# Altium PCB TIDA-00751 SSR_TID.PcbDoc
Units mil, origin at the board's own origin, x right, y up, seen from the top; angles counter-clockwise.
Board outline 5000 x 2000 mil, 2 copper layers (Top Layer, Bottom Layer), stack 62 mil thick; 77 components, 33 nets, 159 pads, 254 vias.
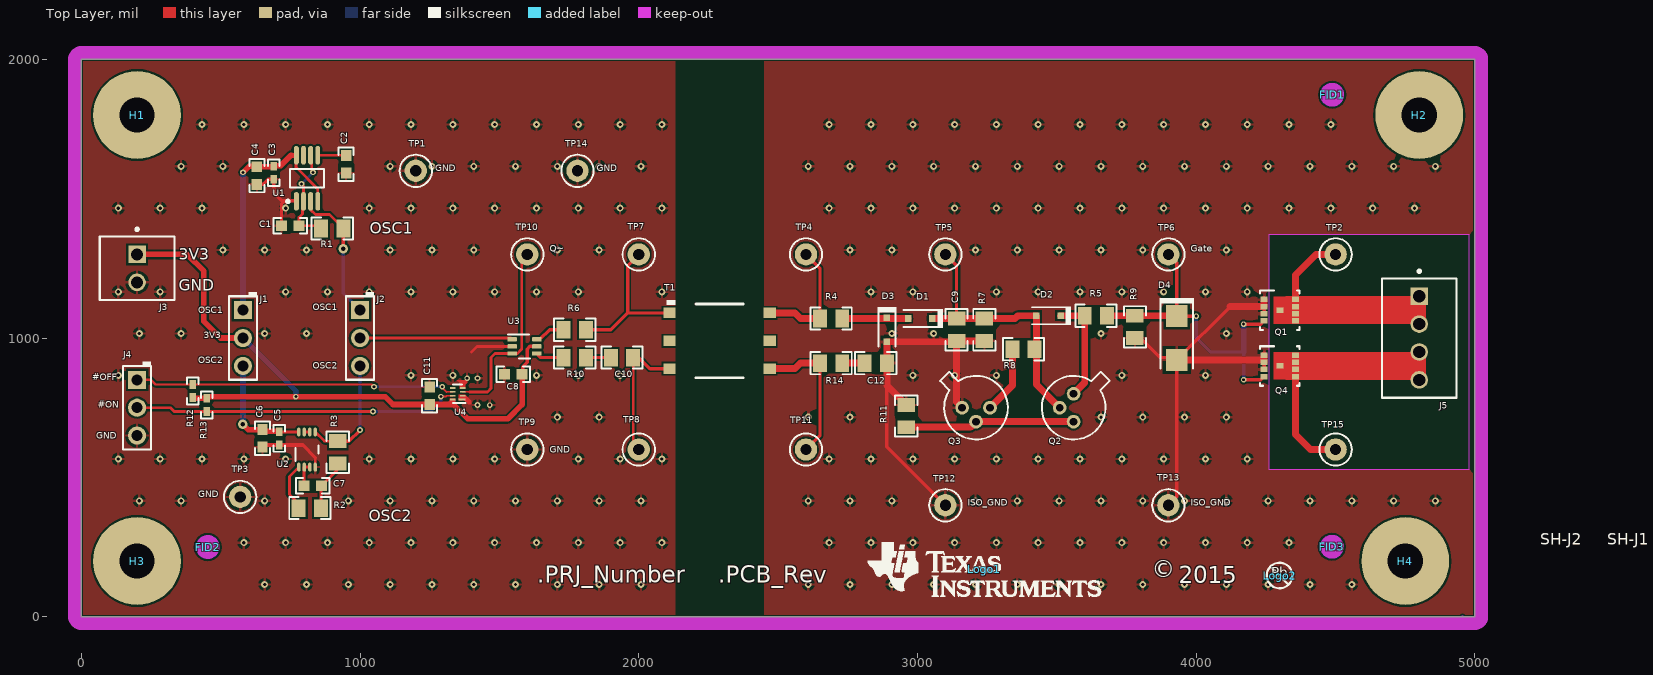
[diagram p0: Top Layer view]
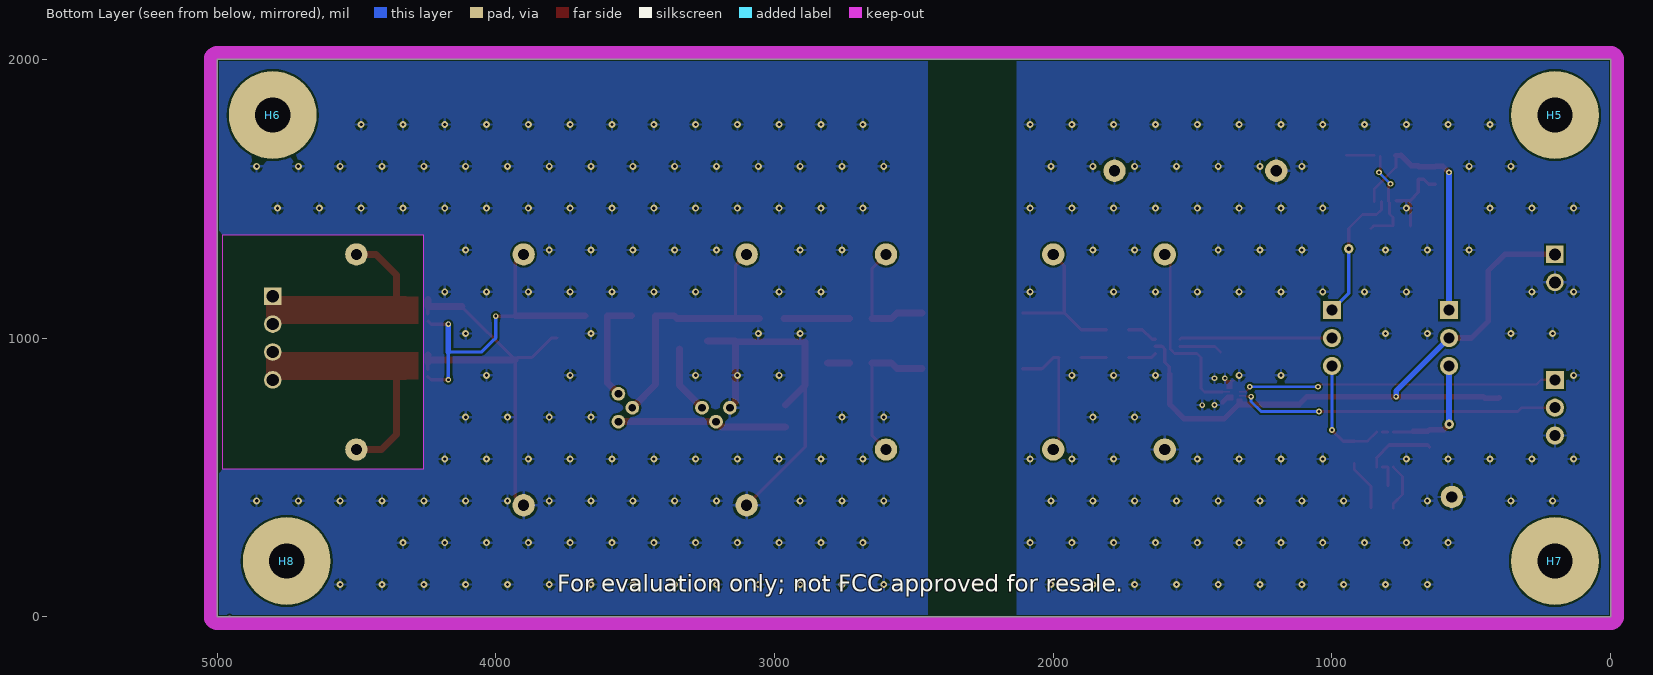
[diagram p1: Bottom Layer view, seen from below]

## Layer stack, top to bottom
Top Solder: solder mask 0.4, Solder Resist, Dk 3.5
Top Layer: signal copper 1.4
Dielectric1: core 59.2, FR-4, Dk 4.8
Bottom Layer: signal copper 1.4
Bottom Solder: solder mask 0.4, Solder Resist, Dk 3.5

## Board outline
0,0 5000,0 5000,2000 0,2000

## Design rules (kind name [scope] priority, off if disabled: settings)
AcuteAngle [All] p1: minimum=4.50000000000000E+0001 checktracksonly=FALSE
AssemblyTestPointUsage [All] p1: valid=2
Clearance Clearance_Q1,Q4 [inComponent('Q1') or inComponent('Q4')] p1: gap=5.5
Clearance Clearance_1 [IsTrack] p2: gap=7
Clearance Clearance_Fill [IsRegion] p3: gap=7
Clearance Clearance_U4 [inComponent('U4')] p4: gap=1
Clearance Clearance_Keepouts [((IsTrack Or IsArc) And Not InPoly) And IsFree and IsKeepOut vs ((IsTrack Or IsArc) And Not InPoly) And IsFree and IsKeepOut] p5: gap=0
Clearance Clearance_BoardEdge_MountingHoles [OnCopper and InComponentClass('Mounting Holes') vs IsKeepOut] p6: gap=40
Clearance Clearance_BoardEdge_Poly [OnCopper and InPoly vs IsKeepOut] p7: gap=25
Clearance Clearance_BoardEdge [OnCopper and Not InComponentClass('Logo') and not InComponentClass('FiducialMark') and not InRegion(1000,500,4000,800) and Not IsKeepout vs IsKeepOut] p8: gap=25
Clearance Clearance_Poly [InPolygon] p9: gap=25
Clearance [All] p10: gap=7.87
ComponentClearance ComponentClearance_MountingHoles_FiducialMarks [InComponentClass('Mounting Holes') vs InComponentClass('FiducialMark')] p1: gap=50 collisioncheckmode=3 verticalgap=10 showdistances=FALSE
ComponentClearance ComponentClearance_Shunt [InComponentClass('Header') vs InComponentClass('Shunt')] p2: gap=0 collisioncheckmode=3 verticalgap=0 showdistances=FALSE
ComponentClearance ComponentClearance_Logo [InComponentClass('Logo')] p3: gap=50 collisioncheckmode=3 verticalgap=10 showdistances=FALSE
ComponentClearance ComponentClearance_ScrewToNut [(HasFootprint('NY PMS 440 0025 PH')) vs (HasFootprint('Keystone_1902C'))] p4: gap=5 collisioncheckmode=3 verticalgap=10 showdistances=FALSE
ComponentClearance ComponentClearance_MountingHoles [InComponentClass('Mounting Holes')] p5: gap=250 collisioncheckmode=3 verticalgap=100000 showdistances=FALSE
ComponentClearance ComponentClearance_SmallPassives [HasFootprint('0201*') or HasFootprint('0402*') or HasFootprint('0508') or HasFootprint('0603*') or HasFootprint('0612') or HasFootprint('0805*') or HasFootprint('0815*') or HasFootprint('0830*') or HasFootprint('1206*') or HasFootprint('1210*') or HasFootprint('1808*') or HasFootprint('1812*') or HasFootprint('1825*') or HasFootprint('2010*') or HasFootprint('2220*') or HasFootprint('2225*') or HasFootprint('2512*') or HasFootprint('2728*') or HasFootprint('3518*') vs HasFootprint('0201*') or HasFootprint('0402*') or HasFootprint('0508') or HasFootprint('0603*') or HasFootprint('0612') or HasFootprint('0805*') or HasFootprint('0815*') or HasFootprint('0830*') or HasFootprint('1206*') or HasFootprint('1210*') or HasFootprint('1808*') or HasFootprint('1812*') or HasFootprint('1825*') or HasFootprint('2010*') or HasFootprint('2220*') or HasFootprint('2225*') or HasFootprint('2512*') or HasFootprint('2728*') or HasFootprint('3518*')] p6: gap=20 collisioncheckmode=3 verticalgap=10 showdistances=FALSE
ComponentClearance ComponentClearance_THtoSMT [IsThruComponent vs IsSMTComponent] p7: gap=100 collisioncheckmode=3 verticalgap=30 showdistances=FALSE
ComponentClearance ComponentClearance_THtoTH [IsThruComponent vs IsThruComponent] p8: gap=118.11 collisioncheckmode=3 verticalgap=30 showdistances=FALSE
ComponentClearance [All] p9: gap=40 collisioncheckmode=3 verticalgap=10 showdistances=FALSE
DiffPairsRouting [All] p1: maxlimit=100 minlimit=10 mostfreqgap=10 toplayer_minwidth=15 toplayer_maxwidth=15 toplayer_prefwidth=15 bottomlayer_minwidth=15 bottomlayer_maxwidth=15 bottomlayer_prefwidth=15 maxuncoupledlength=1000
FabricationTestPointUsage TestPointUsage [All] p1: valid=2 allowmultiple=FALSE
FabricationTestpoint Testpoint [All] p1: side=3 testpointundercomponent=TRUE minsize=40 maxsize=100 preferedsize=60 minholesize=0 maxholesize=40 preferedholesize=32 testpointgrid=1 allowsidetop=TRUE allowsidebottom=TRUE usegrid=TRUE gridtolerance=0.01
FanoutControl Fanout_LCC [IsLCC] p1: bgadir=Out bgaviamode=Centered fanoutstyle=Auto fanoutdirection=Alternating viagrid=1 // Fanout_LCC (Default Rule)
FanoutControl Fanout_BGA [IsBGA] p2: bgadir=Out bgaviamode=Centered fanoutstyle=Auto fanoutdirection=Alternating viagrid=1 // Fanout_BGA (Default Rule)
FanoutControl Fanout_Default [All] p4: bgadir=Out bgaviamode=Centered fanoutstyle=Auto fanoutdirection=Alternating viagrid=1 // Fanout_Default (Default Rule)
FanoutControl Fanout_Small [(CompPinCount < 5)] p5: bgadir=Out bgaviamode=Centered fanoutstyle=Auto fanoutdirection=OutThenIn viagrid=1 // Fanout_Small (Default Rule)
HoleSize [All] p1: absolutevalues=TRUE maxlimit=251 minlimit=8 maxpercent=80.000 minpercent=20.000
MinimumAnnularRing MinimumAnnularRing_ThermalPadVias [IsVia and InAnyComponent] p1: minimumring=5
MinimumAnnularRing [All] p2: minimumring=5
MinimumSolderMaskSliver MinimumSolderMaskSliver_Logo [InComponentClass('Logo') vs InComponentClass('Logo')] p1: minsoldermaskwidth=0.7
MinimumSolderMaskSliver [All] p2: minsoldermaskwidth=1.9
PlaneConnect [All] p1: planeconnectstyle=Relief reliefexpansion=10 reliefentries=4 reliefconductorwidth=10 reliefairgap=10
PolygonConnect [All] p1: connectstyle=Relief reliefconductorwidth=10 reliefentries=4 polygonreliefangle="90 Angle" airgapwidth=10
RoutingVias ThermalPadVias [IsVia and InAnyComponent] p1: holewidth=7.87 width=19.68 viastyle="Through Hole" minholewidth=7.87 minwidth=19.68 maxholewidth=12.99 maxwidth=23.62
RoutingVias [All] p2: holewidth=16 width=34 viastyle="Through Hole" minholewidth=7.87 minwidth=20 maxholewidth=40 maxwidth=65
SilkToBoardRegionClearance [Not ((IsComment or IsDesignator) And (Hide <> 'False')) and not InRegion(1000,500,4000,800)] p1:
SilkToSilkClearance SilkToSilkClearance_Pb-FreeLogo [(HasFootprint('Pb-Free_Overlay_Medium') OR HasFootprint('Pb-Free_Overlay_Small')) vs (HasFootprint('Pb-Free_Overlay_Medium') OR HasFootprint('Pb-Free_Overlay_Small'))] p1: silktosilkclearance=0
SilkToSilkClearance [All] p2: silktosilkclearance=4
SilkToSolderMaskClearance SilkToComonentPadClearance [IsPad and InAnycomponent] p1: minsilkscreentomaskgap=5 clearancetoexposedcopper=TRUE
SilkToSolderMaskClearance "Silk to Solder Mask Opening" [All] p2: minsilkscreentomaskgap=4 clearancetoexposedcopper=FALSE
SolderMaskExpansion [All] p1: expansion=1.97
UnpouredPolygon [All] p1: allowunpoured=FALSE
Width [All] p1: maxlimit=100 minlimit=6 preferedwidth=10 checkconnectedcopper=TRUE
14 further rules are at their usual default settings.

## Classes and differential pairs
component class "Mounting Holes": H1 H2 H3 H4
component class Logo: Logo1
component class "TIDA-00751 SSR_TID_Hardware": FID1 FID2 FID3 H1 H2 H3 H4 H5 H6 H7 H8 Logo1 Logo2 ZZ1 ZZ2 ZZ3
component class FiducialMark: FID1 FID2 FID3
component class AssemblyNote: ZZ1 ZZ2 ZZ3
component class Header: J1 J2 J4
component class "TIDA-00751 SSR_OSC+Relay": C1 C2 C3 C4 C5 C6 C7 C8 C9 C10 C11 C12 D1 D2 D3 D4 J1 J2 J3 J4 J5 Q1 Q2 Q3 Q4 R1 R2 R3 R4 R5 R6 R7 R8 R9 R10 R11 R12 R13 R14 SH-J1 SH-J2 T1 TP1 TP2 TP3 TP4 TP5 TP6 TP7 TP8 TP9 TP10 TP11 TP12 TP13 TP14 TP15 U1 U2 U3 U4
component class Shunt: SH-J1 SH-J2

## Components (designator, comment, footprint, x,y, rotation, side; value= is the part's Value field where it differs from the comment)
C1 "GRM1885C1H101JA01D" 0603 750,1402.99 r180 top
C2 "GRM188R71E103KA01D" 0603 950,1622.99 r270 top
C3 "C1005X5R1A104K050BA" 0402 690,1592.99 r90 top
C4 "GRM188R61E105KA12D" 0603 630,1582.99 r90 top
C5 "C1005X5R1A104K050BA" 0402 710,640 r90 top
C6 "GRM188R61E105KA12D" 0603 650,640 r90 top
C7 "GRM1885C1H101JA01D" 0603 830,470 r0 top
C8 "GRM188R61E105KA12D" 0603 1550,870 r180 top
C9 "08051A101FAT2A" 0805_HV 3140,1030 r270 top
C10 "GRM21BR61E106KA73L" 0805_HV 1940,930 r0 top
C11 "GRM188R71C104KA01D" 0603 1249.59,793.11 r270 top
C12 "GRM2195C1H562JA01D" 0805_HV 2850,910 r180 top
D1 "1N4448WX-TP" sod-323 3010,1070 r180 top
D2 "1N4448WX-TP" sod-323 3470,1080 r180 top
D3 "1N4448WX-TP" sod-323 2890,1030 r270 top
D4 "SMAZ18-13-F" SMA 3930,1000 r270 top
FID1 "Fiducial" Fiducial10-20 4487.5,1872.7 r0 top
FID2 "Fiducial" Fiducial10-20 453.7,250.2 r0 top
FID3 "Fiducial" Fiducial10-20 4486.6,251.4 r0 top
H1 "NY PMS 440 0025 PH" "NY PMS 440 0025 PH" 200,1800 r0 top locked
H2 "NY PMS 440 0025 PH" "NY PMS 440 0025 PH" 4800,1800 r0 top locked
H3 "NY PMS 440 0025 PH" "NY PMS 440 0025 PH" 200,200 r0 top locked
H4 "NY PMS 440 0025 PH" "NY PMS 440 0025 PH" 4750,200 r0 top locked
H5 "1902C" Keystone_1902C 200,1800 r180 bottom locked
H6 "1902C" Keystone_1902C 4800,1800 r180 bottom locked
H7 "1902C" Keystone_1902C 200,200 r180 bottom locked
H8 "1902C" Keystone_1902C 4750,200 r180 bottom locked
J1 "5-146278-3" TE_5-146278-3 580,1000 r270 top
J2 "5-146278-3" TE_5-146278-3 1000,1000 r270 top
J3 "282834-2" TEC_282834-2 200,1250 r270 top
J4 "5-146278-3" TE_5-146278-3 200,750 r270 top
J5 "282834-4" TEC_282834-4 4800,1000 r270 top
Logo1 "Texas Instruments" TI_Stacked_Overlay_Small 3240,170 r0 top
Logo2 "Pb-Free Symbol" Pb-Free_Overlay_Small 4298.8,147.9 r0 top
Q1 "CSD19537Q3" DQG0008A 4300,1100 r0 top
Q2 "2N2907A" TO-18 3560,750 r0 top
Q3 "2N2222A" TO-18 3210,750 r90 top
Q4 "CSD19537Q3" DQG0008A 4300,900 r0 top
R1 "CRCW080516K2FKEA" 0805_HV 900,1392.99 r0 top
R2 "CRCW080511K5FKEA" 0805_HV 820,390 r0 top
R3 "CRCW080511K5FKEA" 0805_HV 920,590 r90 top
R4 "CRCW08050000Z0EA" 0805_HV 2690,1070 r0 top
R5 "CRCW08050000Z0EA" 0805_HV 3640,1080 r0 top
R6 "CRCW08050000Z0EA" 0805_HV 1770,1030 r0 top
R7 "CRCW0805422KFKEA" 0805_HV 3240,1030 r270 top
R8 "RT0805BRD07505RL" 0805_HV 3380,960 r180 top
R9 "CRCW0805422KFKEA" 0805_HV 3780,1040 r90 top
R10 "CRCW08050000Z0EA" 0805_HV 1770,930 r0 top
R11 "ERJ-P06F1001V" 0805_HV 2960,720 r90 top
R12 "CRCW0402100KJNED" 0402 400,810 r270 top
R13 "CRCW0402100KJNED" 0402 450,760 r90 top
R14 "CRCW08050000Z0EA" 0805_HV 2690,910 r0 top
SH-J1 "2SN-BK-G" 2SN-BK-G 5510,150 r90 top
SH-J2 "2SN-BK-G" 2SN-BK-G 5270,150 r90 top
T1 "760390014" Wurth_760390013 2290,990 r0 top
TP1 "5001" Keystone5001 1200,1600 r0 top
TP2 "5004" Keystone5004 4500,1300 r0 top
TP3 "5001" Keystone5001 570,430 r0 top
TP4 "5004" Keystone5004 2600,1300 r0 top
TP5 "5004" Keystone5004 3100,1300 r0 top
TP6 "5004" Keystone5004 3900,1300 r0 top
TP7 "5004" Keystone5004 2000,1300 r0 top
TP8 "5003" Keystone5003 2000,600 r0 top
TP9 "5001" Keystone5001 1600,600 r0 top
TP10 "5004" Keystone5004 1600,1300 r0 top
TP11 "5003" Keystone5003 2600,600 r0 top
TP12 "5001" Keystone5001 3100,400 r0 top
TP13 "5001" Keystone5001 3900,400 r0 top
TP14 "5001" Keystone5001 1780,1600 r0 top
TP15 "5004" Keystone5004 4500,600 r0 top
U1 "LMC555CMM/NOPB" MUA08A_N 810,1572.99 r90 top
U2 "SN74AUP3G14DCUR" DCU0008A_N 810,600 r90 top
U3 "SN74LVC1G19DCKR" DCK0006A_N 1590,970 r0 top
U4 "SN74AUP1G74DQER" DQE0008A 1350,800 r180 top
ZZ1 "These assemblies are ESD sensitive, ESD precautions shall be observed." AssemblyNote 185,3829.11 r0 top
ZZ2 "These assemblies must be clean and free from flux and all contaminants. Use of no clean flux is not acceptable." AssemblyNote 185,3740.56 r0 top
ZZ3 "These assemblies must comply with workmanship standards IPC-A-610 Class 2, unless otherwise specified." AssemblyNote 185,3652 r0 top

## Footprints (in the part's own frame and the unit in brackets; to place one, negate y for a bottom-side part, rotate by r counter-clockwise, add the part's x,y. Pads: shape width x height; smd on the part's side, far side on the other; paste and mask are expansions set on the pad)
2SN-BK-G [mil] "Samtec STEP model"
  round 1 on Mech3: 0(0,0)
  body extent -78,-39 79,39, height 188
0402 [mm] "0402 from SM-752 data"
  rect 0.8x0.6 smd: 1(-0.6,0) 2(0.6,0)
  silkscreen extent -1.22,-0.52 1.22,0.52, body extent -0.55,-0.3 0.55,0.3, height 0.6
0603 [mm] "0603 from SM-752 data"
  rect 1x0.95 smd: 1(-0.8,0) 2(0.8,0)
  silkscreen extent -1.52,-0.69 1.52,0.69, body extent -0.87,-0.47 0.87,0.47, height 1
0805_HV [mil] "0805 with 30mil clearance between pads"
  rect 50x63 smd: 1(-40,0) 2(40,0)
  silkscreen extent -74,-40 74,40, body extent -43,-29 43,29, height 57
AssemblyNote [mil] "Assembly Note"
DCK0006A_N [mm] "SOT23, 6-Leads, Body 2x1.3mm, Pitch 0.65mm, Lead Span 2.1mm, IPC Medium Density"
  rrect25% 0.85x0.4 smd: 1(-1.125,0.65) 2(-1.125,0) 3(-1.125,-0.65) 4(1.125,-0.65) 5(1.125,0) 6(1.125,0.65)
  silkscreen extent -1.5,-1.09 0.51,1.09, body extent -1.14,-1 1.14,1, height 0.95
DCU0008A_N [mm] "TSSOP, 8-Leads, Body 2x2.3mm, Pitch 0.5mm, IPC Medium Density"
  oval 0.8x0.3 smd: 1(-1.6,0.75) 2(-1.6,0.25) 3(-1.6,-0.25) 4(-1.6,-0.75) 5(1.6,-0.75) 6(1.6,-0.25) 7(1.6,0.25) 8(1.6,0.75)
  silkscreen extent -1.05,-1.05 0.38,1.05, body extent -1.56,-1 1.56,1, height 0.9
DQE0008A [mm] "SON, 8-Leads, Body 1.4x1mm, Pitch 0.35mm, TI Recommended"
  rect 0.6x0.16 smd: 1(-0.4,0.525)
  rect 0.5x0.16 smd: 2(-0.45,0.175) 3(-0.45,-0.175) 4(-0.45,-0.525) 5(0.45,-0.525) 6(0.45,-0.175) 7(0.45,0.175) 8(0.45,0.525)
  silkscreen extent -0.7,-0.85 0.4,0.85, body extent -0.53,-0.72 0.53,0.73, height 0.41
DQG0008A [mm] "SMD, 8-Leads, Body 3.3x3.3mm, Pitch 0.65mm"
  rect 0.63x0.5 smd paste-0.4: 1(-1.435,0.975) 2(-1.435,0.325) 3(-1.435,-0.325) 4(-1.435,-0.975) 5(1.435,-0.975) 6(1.435,-0.325) 7(1.435,0.325) 8(1.435,0.975) 9(0,0)
  Top Layer region: -0.56,1.225 -0.56,-1.225 1.34,-1.225 1.34,1.225
  silkscreen extent -1.8,-1.8 1.8,1.8, body extent -1.65,-1.65 1.65,1.65, height 1.1
Fiducial10-20 [mm]
  round 1 smd mask+0.5: 1(0,0)
  Top Layer keep-out circle w1.178: c0,0 r0.5
Keystone5001 [mil] "For Keystone 500x miniature loop terminals"
  round 80 hole 40: 1(0,0)
  silkscreen extent -58,-58 58,58, body extent -49,-49 49,49, height 182
Keystone5003 [mil] "For Keystone 500x miniature loop terminals"
  round 80 hole 40: 1(0,0)
  silkscreen extent -58,-58 58,58, body extent -49,-49 49,49, height 182
Keystone5004 [mil] "For Keystone 500x miniature loop terminals"
  round 80 hole 40: 1(0,0)
  silkscreen extent -58,-58 58,58, body extent -49,-49 49,49, height 182
Keystone_1902C [mil] "Hex Standoff, 4-40 threaded, nylon"
  body extent -145,-126 146,126, height 501
MUA08A_N [mm] "TSOP, 8-Leads, Body 3x3mm, Pitch 0.65mm, IPC Medium Density"
  oval 1.7x0.45 smd: 1(-2.1,0.975) 2(-2.1,0.325) 3(-2.1,-0.325) 4(-2.1,-0.975) 5(2.1,-0.975) 6(2.1,-0.325) 7(2.1,0.325) 8(2.1,0.975)
  silkscreen extent -2.22,-1.55 0.85,1.87, body extent -1.6,-1.6 1.6,1.6, height 1.09
"NY PMS 440 0025 PH" [mm] "4-40 nylon screw and mounting hole"
  round 8 hole 3.2: 1(0,0)
  body extent -3.3,-3.3 3.3,3.3, height 2.69
Pb-Free_Overlay_Small [mil]
  silkscreen extent -46,-46 46,46
SMA [mm] "Molded Diode, 2-Leads, Body 4.3x2.6mm, IPC Medium Density, based on OnSemi component dimensions and land pattern"
  rect 2x2 smd: 1(-2,0) 2(2,0)
  silkscreen extent -3.66,-1.57 2.79,1.57, body extent -2.6,-1.3 2.6,1.3, height 2.42
sod-323 [mm] "NXP recommended land pattern"
  rect 0.6x0.6 smd paste-0.05: 1(-1.1,0) 2(1.1,0)
  silkscreen extent -2.06,-0.86 1.53,0.86, body extent -1.3,-0.67 1.3,0.68, height 1.1
TE_5-146278-3 [mm] "TE CONNECTIVITY"
  rect 1.65x1.65 hole 1: 1(-2.54,0)
  round 1.65 hole 1: 2(0,0) 3(2.54,0)
  silkscreen extent -4.19,-1.27 3.81,1.27, body extent -3.68,-1.17 3.68,1.17, height 8.13
TEC_282834-2 [mm] "TEC"
  rect 1.6x1.6 hole 1.1: 1(-1.27,0)
  round 1.6 hole 1.1: 2(1.27,0)
  silkscreen extent -3.66,-3.4 2.9,3.4, body extent -2.77,-3.25 2.77,3.25, height 10.01
TEC_282834-4 [mm] "TEC"
  rect 1.6x1.6 hole 1.1: 1(-3.81,0)
  round 1.6 hole 1.1: 2(-1.27,0) 3(1.27,0) 4(3.81,0)
  silkscreen extent -6.2,-3.4 5.44,3.4, body extent -5.31,-3.25 5.31,3.25, height 10.02
TI_Stacked_Overlay_Small [mil]
  silkscreen extent -418,-98 418,98
TO-18 [mm] "STM dimensions used"
  round 1.25 hole 0.711: 1(-1.27,0) 2(0,-1.27) 3(0,1.27)
  silkscreen extent -2.89,-2.9 3.27,3.27, body extent -2.88,-2.88 3.27,3.27, height 5.3
Wurth_760390013 [mil] "Wurth"
  rect 44x38 smd: 1(-180,100) 2(-180,0) 3(-180,-100) 4(180,-100) 5(180,0) 6(180,100)
  silkscreen extent -190,-132 85,145, body extent -198,-135 198,130, height 166

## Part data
C1 C7: "CAP, CERM, 100 pF, 50 V, +/- 5%, C0G/NP0, 0603"
C2: "CAP, CERM, 0.01 µF, 25 V, +/- 10%, X7R, 0603"
C3 C5: "CAP, CERM, 0.1 µF, 10 V, +/- 10%, X5R, 0402"
C4 C6 C8: "CAP, CERM, 1 µF, 25 V, +/- 10%, X5R, 0603"
C9: "CAP, CERM, 100 pF, 100 V, +/- 1%, C0G/NP0, 0805"
C10: "CAP, CERM, 10 µF, 25 V, +/- 10%, X5R, 0805"
C11: "CAP, CERM, 0.1 µF, 16 V, +/- 10%, X7R, 0603"
C12: "CAP, CERM, 5600 pF, 50 V, +/- 5%, C0G/NP0, 0805"
D1 D2 D3: "Diode, Switching, 75 V, 0.25 A, SOD-323"
D4: "Diode, Zener, 18 V, 1 W, AEC-Q101, SMA"
FID1 FID2 FID3: "Fiducial mark.  There is nothing to buy or mount."
H1 H2 H3 H4: "Machine Screw, Round, #4-40 x 1/4, Nylon, Philips panhead"
H5 H6 H7 H8: "Standoff, Hex, 0.5\"L #4-40 Nylon"
J1 J2 J4: "Header, 100mil, 3x1, Tin, TH"
J3: "Terminal Block, 2x1, 2.54mm, TH"
J5: "Terminal Block, 100mil, 4X1 TH"
Logo1: library part TI_Logo, "Texas Instrument Corporate Signature"
Logo2: library part Pb-Free
Q1 Q4: "MOSFET, N-CH, 100 V, 50 A, DQG0008A"
Q2: library part "2N2907A, Central Semiconductor", "Transistor, PNP, 60 V, 0.6 A, TO-18"
Q3: library part "2N2222A, STMicroelectronics", "Transistor, NPN, 40 V, 0.6 A, TO-18"
R1: "RES, 16.2 k, 1%, 0.125 W, 0805"
R2 R3: "RES, 11.5 k, 1%, 0.125 W, 0805"
R4 R5 R6 R10 R14: "RES, 0, 5%, 0.125 W, 0805"
R7 R9: "RES, 422 k, 1%, 0.125 W, 0805"
R8: "RES, 505, 0.1%, 0.125 W, 0805"
R11: "RES, 1.00 k, 1%, 0.25 W, 0805"
R12 R13: "RES, 100 k, 5%, 0.063 W, 0402"
SH-J1 SH-J2: "Shunt, 2mm, Gold plated, Black"
T1: "Transformer, 475uH, SMT"
TP1 TP3 TP9 TP12 TP13 TP14: "Test Point, Miniature, Black, TH"
TP2 TP4 TP5 TP6 TP7 TP10 TP15: "Test Point, Miniature, Yellow, TH"
TP8 TP11: "Test Point, Miniature, Orange, TH"
U1: "CMOS Timer, 8-pin Mini SOIC, Pb-Free"
U2: "LOW-POWER TRIPLE SCHMITT-TRIGGER INVERTER, DCU0008A"
U3: "1-OF-2 DECODER/DEMULTIPLEXER, DCK0006A"
U4: "LOW-POWER SINGLE POSITIVE-EDGE-TRIGGERED D-TYPE FLIP-FLOP WITH CLEAR AND PRESET, DQE0008A"
ZZ1 ZZ2 ZZ3: library part AssemblyNote

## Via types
v1: diameter 25, hole 12, Top Layer to Bottom Layer, tented both sides, 236 vias
v2: diameter 20, hole 10, Top Layer to Bottom Layer, tented both sides, 16 vias
v3: diameter 34, hole 16, Top Layer to Bottom Layer, tented both sides, 2 vias

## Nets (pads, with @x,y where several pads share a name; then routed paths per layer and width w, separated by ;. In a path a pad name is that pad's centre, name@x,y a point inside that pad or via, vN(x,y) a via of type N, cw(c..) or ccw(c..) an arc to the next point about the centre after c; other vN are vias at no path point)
1Y: U2.6 U2.7 | length 19.7
  Top Layer w10: U2.7 U2.6
3V3: C8.1 C11.2 J1.2 J3.1 R12.2 R13.2 U3.5 U4.8 | length 2377.3
  Top Layer w12: C8.1 1584,872.5 1584,897.2 1600,913.2 1600,960 1609.68,969.68 1609.68,970 U3.5
  Top Layer w20: J3.1 380,1300 440,1240 440,1060 500,1000 J1.2 ; R12.2 402.76,783.62 R13.2 ; R13.2@451.1,784.72 456.38,790 v2(770,790) 1090,790 1118.39,761.61 C11.2 1321.61,761.61 ; 1328.5,768.5 1387,710 1530,710 1581.5,761.5 C8.1
  Bottom Layer w20: J1.2 770,810 v2(770,790)
3Y: C7.1 U2.2 U2.3 | length 86.5
  Top Layer w10: C7.1 799.25,470 U2.2@799.25,536.1 ; U2.2 U2.3
GND: C1.2 C2.2 C3.1 C4.1 C5.1 C6.1 C8.2 C11.1 J3.2 J4.3 TP1.1 TP3.1 TP9.1 TP14.1 U1.1 U2.4 U3.2 U4.1 U4.2 U4.4 | length 699.2
  Top Layer w10: U2.4 839.53,570.47 ; 1400,950 1420,970 U3.2
  Top Layer w12: C4.1 653,1551.5 670.88,1569.37 C3.1 690,1522.99 720,1492.99 730,1492.99 ; C6.1 C6.1@657.87,616.38 ; C1.2 718.5,1481.5 730,1492.99 ; U1.1@768.94,1492.99 730,1492.99 ; 793.62,616.38 839.53,570.47
  Top Layer w15: C6.1@657.87,616.38 C5.1 793.62,616.38
  other v1: 658,116 808,116 958,116 1108,116 1258,116 1408,116 1558,116 1708,116 1858,116 2008,116 583,266 733,266 883,266 1033,266 1183,266 1333,266 1483,266 1633,266 1783,266 1933,266 2083,266 208,416 358,416 658,416 958,416 1108,416 1258,416 1408,416 1558,416 1708,416 1858,416 2008,416 133,566 283,566 433,566 583,566 733,566 1033,566 1183,566 1333,566 1483,566 1783,566 1933,566 2083,566 1708,716 1858,716 133,866 1183,866 1333,866 1633,866 1783,866 1933,866 208,1016 358,1016 658,1016 808,1016 133,1166 283,1166 733,1166 883,1166 1033,1166 1183,1166 1333,1166 1483,1166 1633,1166 1783,1166 2083,1166 508,1316 658,1316 808,1316 1108,1316 1258,1316 1408,1316 1708,1316 1858,1316 133,1466 283,1466 433,1466 733,1466 1033,1466 1183,1466 1333,1466 1483,1466 1633,1466 1783,1466 1933,1466 2083,1466 358,1616 508,1616 1108,1616 1258,1616 1408,1616 1558,1616 1708,1616 1858,1616 2008,1616 433,1766 583,1766 733,1766 883,1766 1033,1766 1183,1766 1333,1766 1483,1766 1633,1766 1783,1766 1933,1766 2083,1766
  other v2: 1421.4,759.7 1465.7,759.5 1384.1,855.5 1421.4,855.5
MOS_SRC: C9.2 C12.1 D3.2 D4.2 Q1.1 Q1.2 Q1.3 Q3.3 Q4.1 Q4.2 Q4.3 R7.2 R9.1 R11.2 TP12.1 TP13.1 | length 2900.8
  Top Layer w12: 2890,830 2890,610 TP12.1 ; C9.2@3136.69,986.69 C9.2 ; R9.1 3801.5,1000 3871.5,930 3921.26,930 D4.2 ; TP13.1 3930,430 D4.2 ; 4121.54,1112.8 D4.2 ; Q4.2@4235.04,921.26 Q4.2 Q4.3 ; Q1.3 Q1.2
  Top Layer w25: R11.2 2890,830 D3.2 C9.2@3136.69,986.69 ; Q3.3 3140,770 C9.2 R7.2 ; D4.2 Q4.2@4235.04,921.26 ; 4121.54,1112.8 Q1.2 Q1.1 ; Q4.2 Q4.1
  other v1: 2608,116 2758,116 2908,116 3058,116 3208,116 3358,116 3508,116 3658,116 3808,116 3958,116 4108,116 4258,116 4408,116 4558,116 2683,266 2833,266 2983,266 3133,266 3283,266 3433,266 3583,266 3733,266 3883,266 4033,266 4183,266 4333,266 2608,416 2758,416 2908,416 3208,416 3358,416 3508,416 3658,416 3808,416 3958,416 4108,416 4258,416 4408,416 4558,416 4708,416 4858,416 2683,566 2833,566 2983,566 3133,566 3283,566 3433,566 3583,566 3733,566 3883,566 4033,566 4183,566 2608,716 2758,716 3658,716 3808,716 3958,716 4108,716 2983,866 3133,866 3283,866 3733,866 4033,866 2908,1016 3058,1016 3658,1016 4108,1016 2833,1166 2983,1166 3283,1166 3433,1166 3583,1166 3733,1166 3883,1166 4033,1166 4183,1166 2758,1316 2908,1316 3208,1316 3358,1316 3508,1316 3658,1316 3808,1316 4108,1316 2683,1466 2833,1466 2983,1466 3133,1466 3283,1466 3433,1466 3583,1466 3733,1466 3883,1466 4033,1466 4183,1466 4333,1466 4483,1466 4633,1466 4783,1466 2608,1616 2758,1616 2908,1616 3058,1616 3208,1616 3358,1616 3508,1616 3658,1616 3808,1616 3958,1616 4108,1616 4258,1616 4408,1616 4558,1616 4708,1616 4858,1616 2683,1766 2833,1766 2983,1766 3133,1766 3283,1766 3433,1766 3583,1766 3733,1766 3883,1766 4033,1766 4183,1766 4333,1766 4483,1766
NetC1_1: C1.1 R1.1 U1.2 U1.6 | length 349.7
  Top Layer w10: 797.2,1545.79 U1.2 793.35,1486.46 793.35,1444.86 781.5,1433.01 C1.1 850,1402.99 R1.1 ; U1.6@826.65,1651.81 826.65,1598.59 v2(831.12,1594.12)
  Bottom Layer w10: v2(790,1552.99) v2(831.12,1594.12)
NetC2_1: C2.1 U1.5 | length 100.4
  Top Layer w10: U1.5 C2.1@948.82,1655.67
NetC7_2: C7.2 R2.2 R3.1 | length 184.9
  Top Layer w10: R2.2 860,468.5 C7.2 920,528.5 R3.1
NetC9_1: C9.1 D1.1 D2.2 Q2.1 R7.1 R8.1 TP5.1 | length 988.6
  Top Layer w12: TP5.1 3140,1260 C9.1
  Top Layer w25: D1.1 C9.1 R7.1 3350,1070 3360,1080 D2.2 3426.69,833.31 Q2.1
NetC10_1: C10.1 R10.2 | length 90
  Top Layer w12: R10.2 C10.1
NetC10_2: C10.2 T1.3 TP8.1 | length 484.9
  Top Layer w10: C10.2 1980,620 TP8.1
  Top Layer w12: C10.2 2000,930 2040,890 T1.3
NetC12_2: C12.2 R14.2 | length 80
  Top Layer w25: R14.2 C12.2
NetD1_2: D1.2 D3.1 R4.2 | length 236.7
  Top Layer w25: R4.2 D1.2
NetD2_1: D2.1 Q2.3 R5.1 | length 383.3
  Top Layer w25: D2.1 R5.1 3600,840 Q2.3
NetD4_1: D4.1 Q1.4 Q4.4 R5.2 R9.2 TP6.1 | length 1176.2
  Top Layer w12: TP6.1 3930,1270 D4.1 v2(4000,1078.74) ; v2(4170,850) 4231.89,850 Q4.4 ; v2(4170,1050) 4231.89,1050 Q1.4@4241.89,1060
  Top Layer w25: R5.2 D4.1@3928.74,1080
  Bottom Layer w12: v2(4000,1078.74) 4000,1000 4010,990 4050,950 4170,950 v2(4170,850)
  Bottom Layer w20: 4170,950 v2(4170,1050)
NetJ5_1: J5.1 J5.2 Q1.5 Q1.6 Q1.7 Q1.8 Q1.9 TP2.1 | length 802.1
  Top Layer w25: Q1.8 4356.5,1226.5 4430,1300 TP2.1
  Top Layer w50: J5.2 J5.1
  Top Layer w100: 4330,1100 4770,1100
NetJ5_3: J5.3 J5.4 Q4.5 Q4.6 Q4.7 Q4.8 Q4.9 TP15.1 | length 913.8
  Top Layer w25: Q4.5 4356.5,653.5 4410,600 TP15.1
  Top Layer w50: J5.4 4800,875 4800,925 J5.3
  Top Layer w100: 4330,900 4770,900
NetQ2_2: Q2.2 Q3.1 R11.1 | length 608.3
  Top Layer w25: R11.1 3190,680 Q3.1 Q2.2
NetQ3_2: Q3.2 R8.2 | length 243.1
  Top Layer w25: Q3.2 3340,830 R8.2
NetR2_1: R2.1 U2.1 | length 175
  Top Layer w10: R2.1 780,405.44 746.44,439 746.44,502.98 U2.1
NetR4_1: R4.1 T1.6 TP4.1 | length 439
  Top Layer w12: TP4.1 2650,1250 R4.1
  Top Layer w25: T1.6 2560,1090 2580,1070 R4.1
NetR6_1: R6.1 U3.6 | length 110
  Top Layer w12: U3.6 1645.59,995.59 1680,1030 R6.1
NetR6_2: R6.2 T1.1 TP7.1 | length 551.4
  Top Layer w12: R6.2 1900,1030 1960,1090 ; TP7.1 1960,1260 1960,1090 ; T1.1 1960,1090
NetR10_1: R10.1 U3.4 | length 101.7
  Top Layer w12: U3.4 1648.7,930 R10.1
NetR14_1: R14.1 T1.4 TP11.1 | length 519
  Top Layer w12: TP11.1 2650,650 R14.1
  Top Layer w25: T1.4 2560,890 2580,910 R14.1
NetTP10_1: TP10.1 U3.3 U4.3 | length 688.4
  Top Layer w6: U4.3 1392.39,806.89
  Top Layer w10: 1392.39,806.89 1456.89,806.89 1470,820 1470,930 1484.41,944.41 U3.3 1564.41,944.41 1580,960 1580,1280 TP10.1
OFF#: J4.1 R12.1 U4.6 | length 1152.5
  Top Layer w6: 1309.61,806.89 U4.6
  Top Layer w7: v2(1295.3,825.3) 1295.3,821.2 1309.61,806.89
  Top Layer w8: J4.1 250,850 266.38,833.62 R12.1 1041.68,833.62 v2(1050,825.3)
  Bottom Layer w8: v2(1050,825.3) v2(1295.3,825.3)
ON#: J4.2 R13.1 U4.7 | length 1180.3
  Top Layer w6: 1307.5,790 1310.61,793.11 U4.7
  Top Layer w8: v2(1290,790) 1307.5,790
  Top Layer w9: v2(1290,790) v2@1293.11,793.11
  Top Layer w10: J4.2 320,750 333.62,736.38 R13.1 v2(1046.38,736.38)
  Bottom Layer w8: v2(1290,790) v2@1293.11,793.11
  Bottom Layer w10: v2(1046.38,736.38) 1253.6,736.38 1290,772.78 v2(1290,790)
OSC1: J2.1 R1.2 U1.3 | length 493
  Top Layer w10: U1.3 822.8,1460.2 840,1442.99 890,1442.99 R1.2
  Top Layer w12: v3(940,1320) R1.2
  Bottom Layer w12: v3(940,1320) 940,1160 J2.1
OSC2: J2.3 R3.2 U2.5 | length 420.7
  Top Layer w10: U2.5 872.52,630 R3.2
  Top Layer w12: R3.2 960,630 v2(1000,670)
  Bottom Layer w12: v2(1000,670) J2.3
OSC_OUT: J2.2 U3.1 | length 547.5
  Top Layer w10: J2.2 1541.3,1000 U3.1
VCC_OSC1: C3.2 C4.2 J1.1 U1.4 U1.8 | length 909.6
  Top Layer w10: U1.8@770,1654.06 770,1612.99 848.39,1534.61 U1.4
  Top Layer w12: C3.2@687.87,1614.49 C3.2 C3.2@691.38,1617.99
  Top Layer w18: 752.68,1655.67 U1.8
  Top Layer w20: v2(580,1594.26) 602.73,1616.99 627.5,1616.99 C4.2 C3.2@687.87,1614.49 ; C3.2@691.38,1617.99 715,1617.99 752.68,1655.67
  Bottom Layer w20: J1.1 v2(580,1594.26)
VCC_OSC2: C5.2 C6.2 J1.3 U2.8 | length 421.7
  Top Layer w10: C6.2 C6.2@656.5,665 ; C5.2@708.62,665 C5.2 710.63,662.99 U2.8
  Top Layer w20: v3(580,690) 598.5,671.5 C6.2 ; C6.2@656.5,665 C5.2@708.62,665
  Bottom Layer w20: v3(580,690) J1.3
pads on no net: FID1.1 FID2.1 FID3.1 H1.1 H2.1 H3.1 H4.1 SH-J1.0 SH-J2.0 T1.2 T1.5 U1.7 U4.5

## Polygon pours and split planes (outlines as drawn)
MOS_SRC on Top Layer "Top Layer-ISO_GND" (solid, remove dead copper, pour order 8): 2450,0 5000,0 5000,2000 2450,2000 2450,0
GND on Top Layer "Top Layer-GND" (solid, remove dead copper, pour order 6): 0,0 2130,0 2130,2000 0,2000 0,0
GND on Bottom Layer "Top Layer-GND" (solid, remove dead copper, pour order 5): 0,0 2130,0 2130,2000 0,2000 0,0
MOS_SRC on Bottom Layer "Top Layer-ISO_GND" (solid, remove dead copper, pour order 7): 2450,0 5000,0 5000,2000 2450,2000 2450,0

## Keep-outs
Keep-Out Layer:
  pour cut-out: 4260,1370 4260,530 4980,530 4980,1370
  lines w10: 4950,-5 ccw(c4950,0) 4955,0 cw(c4950,0) 4950,-5
  lines w47.24: -23.62,0 ccw(c0,0) 0,-23.62 ; -23.62,0 ccw(c0,0) 0,-23.62 ; -23.62,0 -23.62,2000 ; -23.62,2000 cw(c0,2000) 0,2023.62 ; -23.62,2000 cw(c0,2000) 0,2023.62 ; 0,-23.62 5000,-23.62 ; 0,2023.62 5000,2023.62 ; 5000,-23.62 ccw(c5000,0) 5023.62,0 ; 5000,-23.62 ccw(c5000,0) 5023.62,0 ; 5000,2023.62 cw(c5000,2000) 5023.62,2000 ; 5000,2023.62 cw(c5000,2000) 5023.62,2000 ; 5023.62,0 5023.62,2000
  text ".Layer_Name" at 577,-858.49 h60

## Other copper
Top Layer:
  pour cut-out: 4635.5,992.9
  region net GND: 1357.8,817.8 1357.8,838.7 1347.2,849.3 1384.3,849.3 1384.3,838.8 1377.5,832 1377.5,817.7
  region net GND: 1353.9,796.2 1377.4,796.2 1398.9,774.7 1398.9,762.6 1388.11,762.6 1374.51,776.2 1353.9,776.2
  region net 3V3: 1322.5,782.4 1322.5,776.5 1318.7,772.7 1318.7,751.6 1342.18,751.6 1341.7,782.5
  text ".Layer_Name" at 577,-858.49 h60
Bottom Layer:
  text ".Layer_Name" at 577,-858.49 h60

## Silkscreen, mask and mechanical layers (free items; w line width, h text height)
Top Overlay:
  text "GND" at 1270,1590 h40
  text "GND" at 1850,1590 h40
  text "OSC1" at 1034,1374.3 h40
  text "Q~" at 1680,1300 h40
  text "Gate" at 3980,1300 h40
  text "3V3" at 350,1280 h40
  text "GND" at 350,1170 h40
  text "OSC1" at 830,1090 h40
  text "OSC1" at 420,1080 h40
  text "3V3" at 440,990 h40
  text "OSC2" at 420,900 h40
  text "OSC2" at 830,880 h40
  text "#OFF" at 40,840 h40
  text "#ON" at 59.09,740.2 h40
  text "GND" at 53.5,629.4 h40
  text "GND" at 1680,580 h40
  text "GND" at 420,420 h40
  text "ISO_GND" at 3180,390 h40
  text "ISO_GND" at 3980,390 h40
  text "OSC2" at 1031.6,342.5 h40
  text ".PRJ_Number" at 1635.2,122.8 h60
  text ".PCB_Rev" at 2284.7,122.8 h60
  text "©" at 3840,120 h105
  text "2015" at 3936.92,120 h60
  text ".Layer_Name" at 577,-858.49 h60
Bottom Overlay:
  text "For evaluation only; not FCC approved for resale." at 3780,90 h60
  text ".Layer_Name" at 577,-858.49 h60
Top Paste:
  text ".Layer_Name" at 577,-858.49 h60
Bottom Paste:
  text ".Layer_Name" at 577,-858.49 h60
Top Solder:
  text ".Layer_Name" at 577,-858.49 h60
  text ".Layer_Name" at 577,-858.49 h60
Bottom Solder:
  text ".Layer_Name" at 577,-858.49 h60
Drill Guide:
  text ".Layer_Name" at 577,-858.49 h60
M1 Board Outline:
  the board outline again, w10
  text ".Layer_Name" at 577,-858.49 h60
M2 Board Dimensions:
  rectangle: 0,-275 125,-150
  rectangle: 125,-400 500,-275
  lines w7: 0,-275 1000,-275 ; 125,-400 125,-150 ; 250,-400 250,-150 ; 500,-400 500,-150 ; 750,-400 750,-150 ; 0,-400 1000,-400 1000,-150 0,-150 0,-400
  text ".Layer_Name" at 577,-858.49 h60
M3 3D STEP Top:
  text ".Layer_Name" at 577,-858.49 h60
M4 3D STEP Bottom:
  text ".Layer_Name" at 577,-858.49 h60
M5 Assembly Top:
  lines w10: -292,-930.17 6308,-930.17 ; -292,-726.83 6310,-726.83 ; -292,-523.5 -292,-1133.5 3713,-1133.5 6310,-1133.5 6310,-523.5 -291.5,-523.5 -291.5,-1133.5 1284,-1133.5 ; 2173,-1133.5 2173,-523.5 ; 3440,-726.83 3440,-523.5 ; 4280,-726.83 4280,-523.5 ; 4902,-1140 4902,-937.17
  text "COMPONENTS MARKED 'DNP' SHOULD NOT BE POPULATED." at 1153.5,-318.5 h60
  text "ASSEMBLY VARIANT:" at 1153,-434 h60
  text ".VariantName" at 2189,-434 h60
  text "PCB VIEWED FROM TOP SIDE" at -228.5,-655.67 h60
  text "BOARD #:" at 2248,-655.67 h60
  text ".PRJ_Number" at 2793.5,-655.67 h60
  text "REV:" at 3638,-655.67 h60
  text ".PCB_Rev" at 3929.5,-655.67 h60
  text "SVN REV:" at 4476,-655.67 h60
  text ".VersionControl_RevNumber" at 4982,-655.67 h60
  text "TID #:" at 2248,-859 h60
  text ".TID" at 2793.5,-859 h60
  text "PLOT NAME =" at -228.5,-1064.34 h60
  text ".plot_File_Name" at 577,-1064.34 h60
  text "GENERATED    :" at 2250,-1064.34 h60
  text ".Print_Date" at 3119.5,-1064.34 h60
  text ".Print_Time" at 3848.5,-1064.34 h60
  text "TEXAS INSTRUMENTS" at 5113,-1064.34 h60
M6 Assembly Bottom:
  lines w10: -292.5,-727.33 6309.5,-727.33 ; -290.5,-930.67 6309.5,-930.67 ; 1115.5,-1140.5 1115.5,-937.67 ; 1737.5,-727.33 1737.5,-524 ; 2577.5,-727.33 2577.5,-524 ; 3844.5,-1134 3844.5,-524 ; 4733.5,-1134 6309,-1134 6309,-524 -292.5,-524 -292.5,-1134 2304.5,-1134 6309.5,-1134 6309.5,-524
  text "COMPONENTS MARKED 'DNP' SHOULD NOT BE POPULATED." at 6102,-318 h60
  text ".VariantName" at 5058,-434 h60
  text "ASSEMBLY VARIANT:" at 6097,-434 h60
  text ".VersionControl_RevNumber" at 1035.5,-656.17 h60
  text "SVN REV:" at 1541.5,-656.17 h60
  text ".PCB_Rev" at 2088,-656.17 h60
  text "REV:" at 2379.5,-656.17 h60
  text ".PRJ_Number" at 3224,-656.17 h60
  text "BOARD #:" at 3769.5,-656.17 h60
  text "PCB VIEWED FROM BOTTOM SIDE" at 6246,-656.17 h60
  text ".TID" at 3224,-859.5 h60
  text "TID #:" at 3769.5,-859.5 h60
  text "TEXAS INSTRUMENTS" at 904.5,-1064.84 h60
  text ".Print_Time" at 2169,-1064.84 h60
  text ".Print_Date" at 2898,-1064.84 h60
  text "GENERATED    :" at 3767.5,-1064.84 h60
  text ".plot_File_Name" at 5440.5,-1064.84 h60
  text "PLOT NAME =" at 6246,-1064.84 h60
M9 Title Sheet:
  drawing of 57 lines, arcs and shapes, not listed
  text "1" at 739.84,8036.5 h70
  text "2" at 3235.5,8036.5 h70
  text "3" at 5724.84,8036.5 h70
  text "4" at 8231.51,8036.5 h70
  text "5" at 10730.5,8036.5 h70
  text "6" at 13235.5,8036.5 h70
  text "A" at -416.5,6893.5 h70
  text "A" at 14383.5,6893.5 h70
  text "B" at -416.5,4513.5 h70
  text "B" at 14383.5,4513.5 h70
  text "C" at -416.5,2138.5 h70
  text "C" at 14383.5,2138.5 h70
  text "PROJECT TITLE:" at 11343.5,277.5 h45
  text ".PRJ_Title" at 11393.5,144.17 h70
  text "DESIGNED FOR:" at 11343.5,-23.5 h45
  text ".PRJ_Customer" at 11393.5,-163.5 h70
  text "D" at -416.5,-231.5 h70
  text "D" at 14383.5,-231.5 h70
  text "FILE NAME:" at 11343.5,-323.5 h45
  text ".PCB_File_Name_No_Path" at 11393.5,-443.5 h70
  text "Texas Instruments (TI) and/or its licensors do not warrant the accuracy or completeness of this specification" at 6374,-605.34 h45
  text "ENGINEER:" at 11343.5,-613.5 h45
  text "LAYOUT BY:" at 12848.5,-613.5 h45
  text "or any information contained therein. TI and/or its licensors do not warrant that this design will meet" at 6329.01,-718 h45
  text ".PRJ_Engineer" at 11393.5,-768.49 h70
  text ".PCB_Layout" at 12899,-768.49 h70
  text "the specifications, will be suitable for your application or fit for any particular purpose, or will operate in" at 6329.01,-830.67 h45
  text ".Layer_Name" at 577,-858.49 h60
  text "ALTIUM DESIGNER VERSION:" at 12848.5,-923.5 h45
  text "an implementation. TI and/or its licensors do not warrant that the design is production worthy. You should" at 6329.01,-943.33 h45
  text "completely validate and test your design implementation to confirm the system functionality for your application." at 6374,-1056 h45
  text ".print_Scale" at 11393.5,-1056.83 h70
  text ".Application_BuildNumber" at 12899,-1056.83 h70
  text "1" at 739.84,-1263.5 h70
  text "2" at 3235.5,-1263.5 h70
  text "3" at 5724.84,-1263.5 h70
  text "4" at 8231.51,-1263.5 h70
  text "5" at 10730.5,-1263.5 h70
  text "6" at 13235.5,-1263.5 h70
M10 Fab Notes:
  drawing of 173 lines, arcs and shapes, not listed
  text "DESIGN INFORMATION" at 12377.02,6201 h60
  text "MIN. TRACK WIDTH:" at 11732.46,6021 h60
  text "6" at 12828.7,6021 h60
  text "MIL" at 12983.46,6021 h60
  text "MIN. CLEARANCE:" at 11732.46,5889 h60
  text "0.2" at 12768.7,5889 h60
  text "mm" at 12983.46,5889 h60
  text "MIN. VIA PAD SIZE:" at 11732.46,5757 h60
  text "24" at 12798.71,5757 h60
  text "MIL" at 12983.46,5757 h60
  text "0.05mm (2MIL)" at 12427.46,5615.29 h60
  text "MINIMUM ANNULAR RING" at 11403.23,5611 h60
  text "EXTERNAL" at 13135.46,5611 h60
  text "PER" at 11603.23,5493 h60
  text "IPC-D-275 CLASS 2 LEVEL C" at 11823.23,5493 h60
  text "MIL, HOLES" at 13311.46,5380.71 h60
  text "+/-" at 12919,5380 h60
  text "+/-" at 13773,5380 h60
  text "REGISTRATION TOLERANCES:" at 11403.23,5375 h60
  text "METAL" at 12603,5375 h60
  text "5" at 13179.2,5375 h60
  text "3" at 14012.2,5375 h60
  text "MIL" at 14128.46,5375 h60
  text "+/-" at 13773,5262 h60
  text "HOLE SIZE TOLERANCE (UNLESS OTHERWISE SPECIFIED):" at 11403.23,5257 h60
  text "3" at 14012.2,5257 h60
  text "MIL" at 14128.46,5257 h60
  text "MATERIAL:" at 11328.46,5047.54 h60
  text "FR-4 High Tg" at 12314.9,4907.21 h60
  text "FR-408" at 11749.46,4898.64 h60
  text "OTHER" at 13237.46,4898.64 h60
  text "X" at 12160,4895 h60
  text "62 MIL (1.6mm) +/-10%" at 12069.56,4735.92 h60
  text "THICKNESS:" at 11403.23,4731.64 h60
  text "X" at 11941.4,4731.64 h60
  text "OTHER" at 13354.46,4731.64 h60
  text "TOLERANCE:" at 11403.23,4573.64 h60
  text "X" at 12242.53,4573.64 h60
  text "ANSI IPC-6012 TYPE 3 CLASS 2" at 12429.48,4573.64 h60
  text "OTHER +/-" at 12429.46,4417.64 h60
  text "BOW & TWIST:" at 11403.23,4260.64 h60
  text "X" at 12242.53,4260.64 h60
  text "ANSI IPC-6012 TYPE 3 CLASS 2" at 12429.48,4260.64 h60
  text "OTHER +/-" at 12429.46,4102.13 h60
  text "DRILLING:" at 11328.46,3963.64 h60
  text "REFERENCE:" at 11403.23,3846.64 h60
  text "X" at 12051.46,3846.64 h60
  text "AS SHOWN" at 12238.46,3846.64 h60
  text "X" at 12952.46,3846.64 h60
  text "NC_DRILL FILES" at 13089.46,3846.64 h60
  text "PTH MIN COPPER THICKNESS:" at 11403.23,3688.64 h60
  text "X" at 12753.46,3688.64 h60
  text "1MIL" at 12890.46,3688.64 h60
  text "OTHER" at 13387.46,3688.64 h60
  text "BOARD FINISH:" at 11328.46,3529.64 h60
  text "SILKSCREEN:" at 11483.68,3411.64 h60
  text "X" at 12432.46,3411.64 h60
  text "TOP" at 12558.46,3411.64 h60
  text "X" at 12942.46,3411.64 h60
  text "BOTTOM" at 13069.46,3411.64 h60
  text "SILKSCREEN COLOR:" at 11483.68,3244.64 h60
  text "X" at 12431.42,3244.64 h60
  text "WHITE" at 12558.46,3244.64 h60
  text "OTHER" at 13069.46,3244.64 h60
  text "X" at 12562.42,3085.44 h60
  text "GREEN" at 12689.46,3085.44 h60
  text "OTHER" at 13307.46,3085.44 h60
  text "SOLDER RESIST COLOR:" at 11483.68,3074.64 h60
  text "X" at 12562.42,2915.44 h60
  text "MATTE" at 12689.46,2915.44 h60
  text "SEMI-GLOSS" at 13307,2914.8 h60
  text "IMMERSION GOLD (ENIG)" at 12389.46,2726.92 h60
  text "ENEPIG" at 13727,2723.64 h60
  text "SURFACE FINISH:" at 11328.46,2722.64 h60
  text "X" at 12202.51,2722.64 h60
  text "IMM. TIN/SILVER OR EQUIV" at 11658,2565.64 h60
  text "OTHER" at 13089.46,2565.64 h60
  text "ARRAY/PANEL:" at 11328.46,2386.64 h60
  text "CUT AND TRIM PER M1 BOARD OUTLINE" at 12389.46,2382.35 h60
  text "N.C. ROUTE" at 12389.46,2230.64 h60
  text "X" at 13068.46,2230.64 h60
  text "V. SCORE" at 13255.46,2230.64 h60
  text "CERTIFICATION:" at 11328.46,2093.64 h60
  text "MATERIALS AND WORKMANSHIP FOR ALL PCBS" at 12053.46,2093.64 h60
  text "TO MEET OR EXCEED THE REQUIREMENTS OF:" at 12053.46,1995.64 h60
  text "X" at 11679.96,1859.13 h60
  text "ANSI IPC-A-600F CLASS ->" at 11818.96,1859.13 h60
  text "X" at 13458.02,1859.13 h60
  text "2" at 13576.96,1859.14 h60
  text "1" at 13261.96,1857.64 h60
  text "3" at 13930.96,1857.64 h60
  text "X" at 12494.02,1699.64 h60
  text "RoHS" at 12630.96,1699.64 h60
  text "OTHER" at 13275.36,1699.64 h60
  text "PER ORDER" at 13672.42,1699.64 h60
  text "ALL BOARDS MUST MEET OR EXCEED UL94-V0 REQUIREMENTS." at 11356,1534 h60
  text "PCB MUST BEAR THE UL94V-0 UL REGISTERED MATERIAL ID NUMBER" at 11356,1414 h60
  text "ADDITIONAL REQUIREMENTS:" at 11328.46,1240.64 h60
  text "MICROSECTION:" at 11403.23,1125.64 h60
  text "YES" at 12308.96,1125.64 h60
  text "REQUIRED" at 13170.46,969.49 h60
  text "BARE BOARD ELEC. TEST:" at 11403.23,966.64 h60
  text "NONE" at 12708.96,966.64 h60
  text "X" at 13043.46,966.64 h60
  text "PER ORDER" at 13762.46,966.64 h60
  text ".Layer_Name" at 577,-858.49 h60
M11 Gerber Information:
  lines w10: -292,-930.17 6308,-930.17 ; -292,-726.83 6310,-726.83 ; -292,-523.5 -292,-1133.5 3713,-1133.5 6310,-1133.5 6310,-523.5 -291.5,-523.5 -291.5,-1133.5 1284,-1133.5 ; 2173,-1133.5 2173,-523.5 ; 3440,-726.83 3440,-523.5 ; 4280,-726.83 4280,-523.5 ; 4902,-1140 4902,-937.17
  text "ALL ARTWORK VIEWED FROM TOP SIDE" at -228.5,-655.67 h60
  text "BOARD #:" at 2248,-655.67 h60
  text ".PRJ_Number" at 2793.5,-655.67 h60
  text "REV:" at 3638,-655.67 h60
  text ".PCB_Rev" at 3929.5,-655.67 h60
  text "SVN REV:" at 4476,-655.67 h60
  text ".VersionControl_RevNumber" at 4982,-655.67 h60
  text "LAYER NAME =" at -228.5,-858.49 h60
  text "TID #:" at 2248,-859 h60
  text ".TID" at 2793.5,-859 h60
  text "PLOT NAME =" at -228.5,-1064.34 h60
  text ".plot_File_Name" at 577,-1064.34 h60
  text "GENERATED    :" at 2250,-1064.34 h60
  text ".Print_Date" at 3119.5,-1064.34 h60
  text ".Print_Time" at 3848.5,-1064.34 h60
  text "TEXAS INSTRUMENTS" at 5113,-1064.34 h60
M12 Stackup:
  drawing of 191 lines, arcs and shapes, not listed
  text "Layer" at 9790.58,7830 h60
  text "Name" at 10200.49,7830 h60
  text "Material" at 11130.23,7830 h60
  text "Thickness" at 11990,7830 h60
  text "Constant" at 12639.84,7830 h60
  text "Board Layer Stack" at 13209.7,7830 h60
  text "1" at 9790.58,7710 h60
  text "Top Overlay" at 10200.49,7710 h60
  text "2" at 9790.58,7590 h60
  text "Top Solder" at 10200.49,7590 h60
  text "Solder Resist" at 11130.23,7590 h60
  text "0.40mil" at 11990,7590 h60
  text "3.5" at 12639.84,7590 h60
  text "3" at 9790.58,7470 h60
  text "Top Layer" at 10200.49,7470 h60
  text "Copper" at 11130.23,7470 h60
  text "1.40mil" at 11990,7470 h60
  text "4" at 9790.58,7350 h60
  text "Dielectric1" at 10200.49,7350 h60
  text "FR-4" at 11130.23,7350 h60
  text "59.20mil" at 11990,7350 h60
  text "4.8" at 12639.84,7350 h60
  text "5" at 9790.58,7230 h60
  text "Bottom Layer" at 10200.49,7230 h60
  text "Copper" at 11130.23,7230 h60
  text "1.40mil" at 11990,7230 h60
  text "6" at 9790.58,7110 h60
  text "Bottom Solder" at 10200.49,7110 h60
  text "Solder Resist" at 11130.23,7110 h60
  text "0.40mil" at 11990,7110 h60
  text "3.5" at 12639.84,7110 h60
  text "7" at 9790.58,6990 h60
  text "Bottom Overlay" at 10200.49,6990 h60
  text ".Layer_Name" at 577,-858.49 h60
M13 Component Bodies Top:
  text ".Layer_Name" at 577,-858.49 h60
M14 Component Bodies Bottom:
  text ".Layer_Name" at 577,-858.49 h60
M15 Courtyards Top:
  text ".Layer_Name" at 577,-858.49 h60
M16 Courtyards Bottom:
  text ".Layer_Name" at 577,-858.49 h60
Drill Drawing:
  circle w1: c5557.9,2885.05 r20.77
  lines w1: 5537.13,2365.79 5578.67,2365.79 5578.67,2407.33 5537.13,2407.33 5537.13,2365.79 ; 5537.13,2490.41 5557.9,2500.79 5578.67,2490.41 5568.28,2511.18 5578.67,2531.95 5557.9,2521.56 5537.13,2531.95 5547.51,2511.18 5537.13,2490.41 ; 5537.13,2625.42 5547.51,2625.42 5557.9,2615.03 5568.28,2625.42 5578.67,2625.42 5568.28,2635.8 5578.67,2646.19 5568.28,2646.19 5557.9,2656.57 5547.51,2646.19 5537.13,2646.19 5547.51,2635.8 5537.13,2625.42 ; 5537.13,2781.19 5578.67,2781.19 5557.9,2739.65 5537.13,2781.19 ; 5537.13,2999.28 5547.51,2999.28 5547.51,2988.9 5568.28,2988.9 5568.28,2999.28 5578.67,2999.28 5578.67,3020.05 5568.28,3020.05 5568.28,3030.44 5547.51,3030.44 5547.51,3020.05 5537.13,3020.05 5537.13,2999.28 ; 5537.13,3134.29 5557.9,3113.52 5578.67,3134.29 5557.9,3155.06 5537.13,3134.29 ; 5537.13,3238.14 5537.13,3248.53 5547.51,3258.91 5537.13,3269.3 5537.13,3279.68 5547.51,3279.68 5557.9,3269.3 5568.28,3279.68 5578.67,3279.68 5578.67,3269.3 5568.28,3258.91 5578.67,3248.53 5578.67,3238.14 5568.28,3238.14 5557.9,3248.53 5547.51,3238.14 5537.13,3238.14
  lines w12: 5480,2328.4 7509.11,2328.4 ; 5480,3325.38 7509.11,3325.38 ; 5828.13,2203.78 5828.13,3450 ; 6170.32,2203.78 6170.32,3450 ; 6817.06,2203.78 6817.06,3450 ; 7086.38,2203.78 7086.38,3450 ; 5480,2203.78 7509.11,2203.78 7509.11,3450 5480,3450 5480,2203.78
  text "Symbol" at 5554.77,3362.76 h72
  text "Quantity" at 5865.52,3362.76 h72
  text "Finished Hole Size" at 6207.7,3362.76 h72
  text "Plated" at 6854.45,3362.76 h72
  text "Hole Type" at 7123.77,3362.76 h72
  text "16" at 5865.52,3238.14 h60
  text "10.00mil (0.254mm)" at 6207.7,3238.14 h60
  text "PTH" at 6854.45,3238.14 h60
  text "Round" at 7123.77,3238.14 h60
  text "236" at 5865.52,3113.52 h60
  text "12.00mil (0.305mm)" at 6207.7,3113.52 h60
  text "PTH" at 6854.45,3113.52 h60
  text "Round" at 7123.77,3113.52 h60
  text "2" at 5865.52,2988.9 h60
  text "16.00mil (0.406mm)" at 6207.7,2988.9 h60
  text "PTH" at 6854.45,2988.9 h60
  text "Round" at 7123.77,2988.9 h60
  text "6" at 5865.52,2864.27 h60
  text "28.00mil (0.711mm)" at 6207.7,2864.27 h60
  text "PTH" at 6854.45,2864.27 h60
  text "Round" at 7123.77,2864.27 h60
  text "9" at 5865.52,2739.65 h60
  text "39.37mil (1.000mm)" at 6207.7,2739.65 h60
  text "PTH" at 6854.45,2739.65 h60
  text "Round" at 7123.77,2739.65 h60
  text "15" at 5865.52,2615.03 h60
  text "40.00mil (1.016mm)" at 6207.7,2615.03 h60
  text "PTH" at 6854.45,2615.03 h60
  text "Round" at 7123.77,2615.03 h60
  text "6" at 5865.52,2490.41 h60
  text "43.31mil (1.100mm)" at 6207.7,2490.41 h60
  text "PTH" at 6854.45,2490.41 h60
  text "Round" at 7123.77,2490.41 h60
  text "4" at 5865.52,2365.79 h60
  text "125.98mil (3.200mm)" at 6207.7,2365.79 h60
  text "PTH" at 6854.45,2365.79 h60
  text "Round" at 7123.77,2365.79 h60
  text "294 Total" at 5865.52,2241.16 h60
  text ".Layer_Name" at 577,-858.49 h60

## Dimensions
0,-400 to 1000,-400 on M2 Board Dimensions
0,0 to 0,2000 on M2 Board Dimensions
0,0 to 5000,0 on M2 Board Dimensions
